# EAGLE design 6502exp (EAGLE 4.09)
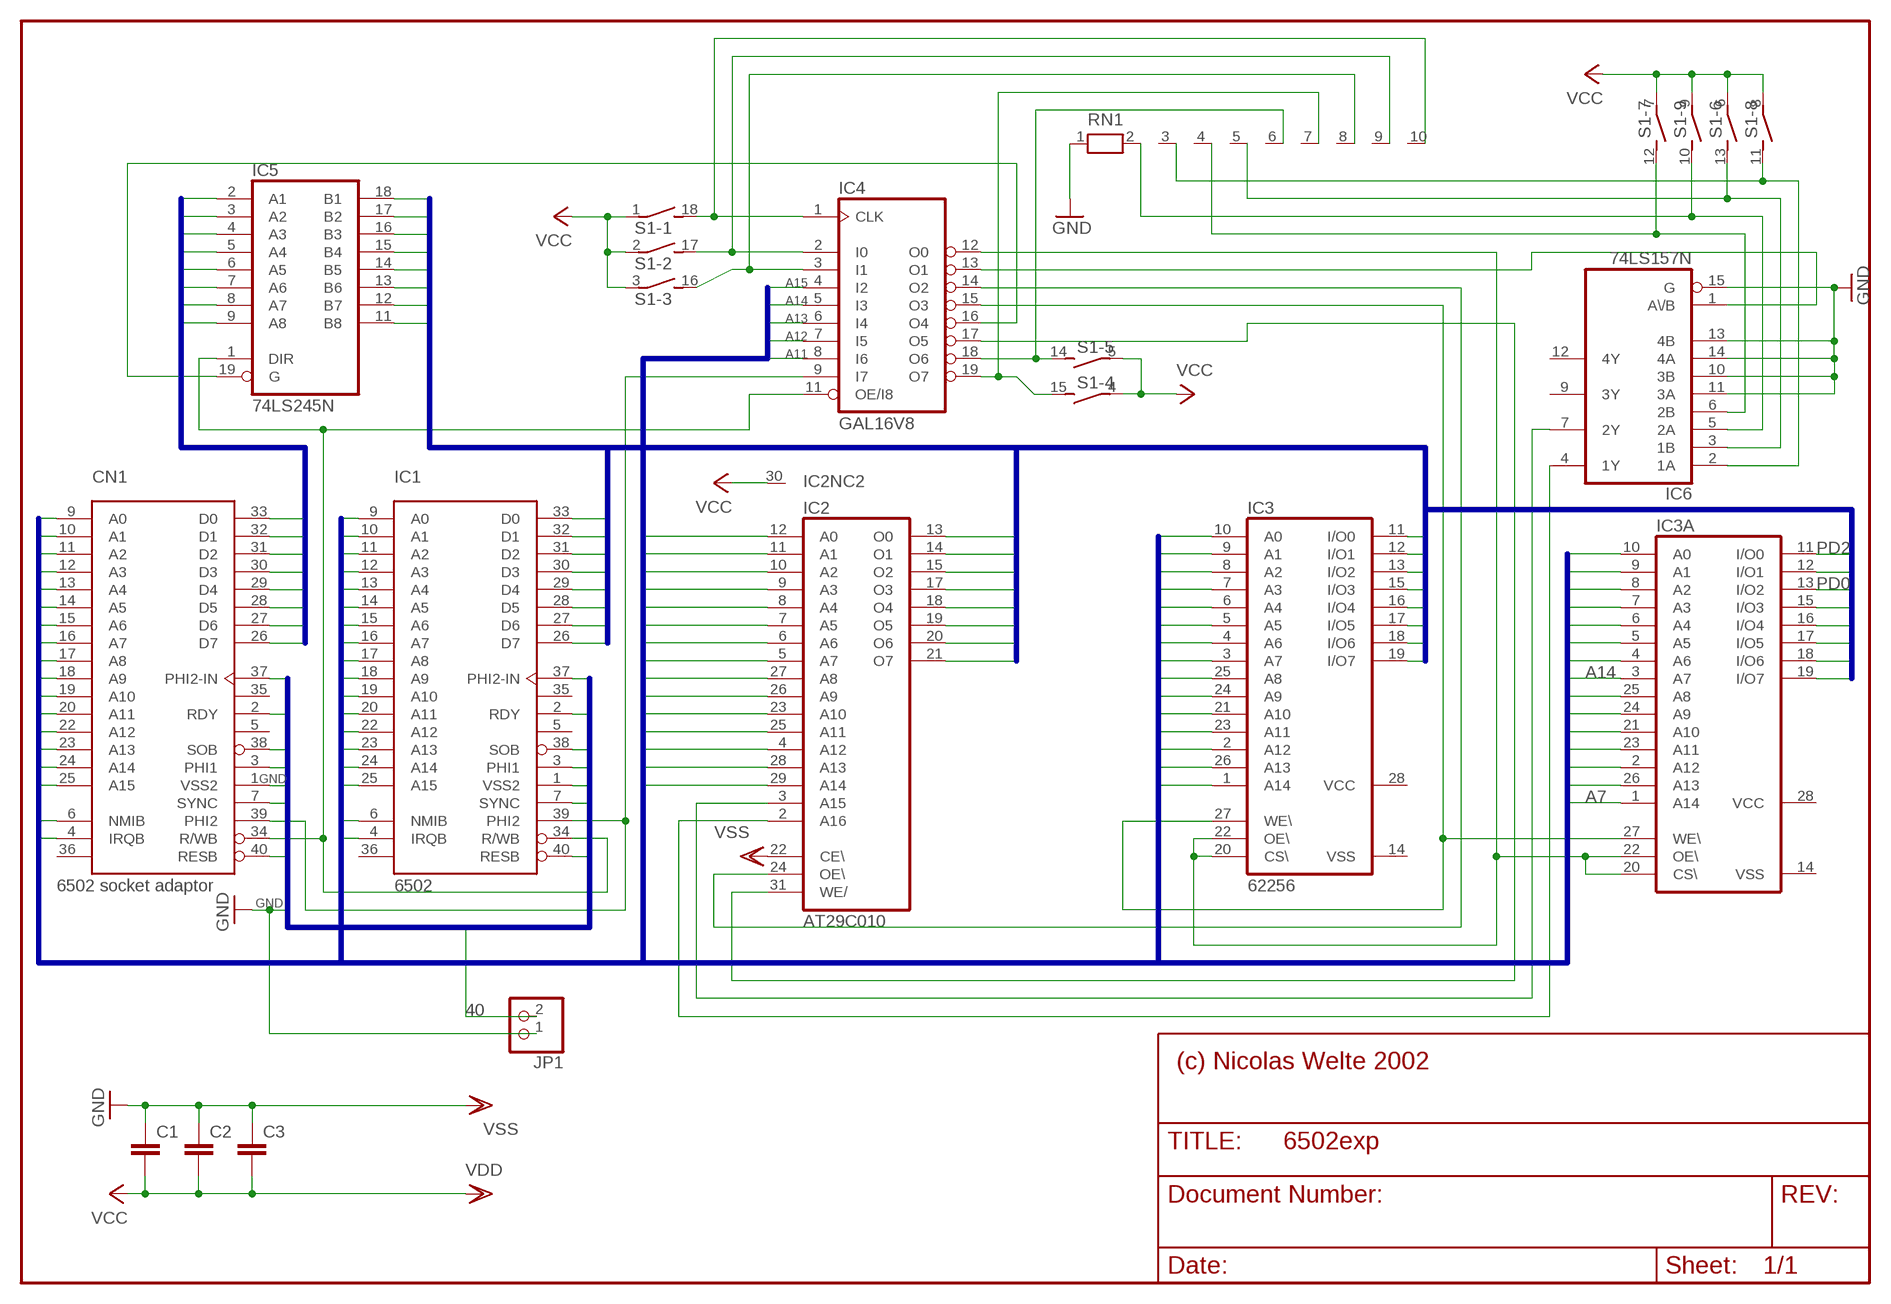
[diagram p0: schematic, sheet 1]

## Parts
C1  C5/3  [C5B3]
C2  C5/3  [C5B3]
C3  C5/3  [C5B3]
CN1  6502 socket adaptor  G65SC02P  [DIP-40]
IC1  6502  G65SC02P  [DIP-40]
IC2  AT29C010  AM29F010P  [DIL32-3]
IC3  62256  62256P  [DIL28-6]
IC3A  62256FP  [SO28L]
IC4  GAL16V8  16V8  [DIL20]
IC5  74LS245N  [DIL20]
IC6  74LS157N  [DIL16]
JP1  PINHD-1X2  [1X02]
RN1  RN09  [RN-10]
S1  DS09E  [DS-09]

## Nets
2: CN1.2(RDY) IC1.2(RDY)
3: CN1.3(PHI1) IC1.3(PHI1)
7: CN1.7(SYNC) IC1.7(SYNC)
37: CN1.37(PHI2-IN) IC1.37(PHI2-IN)
38: CN1.38(SOB) IC1.38(SOB)
40: CN1.40(RESB) IC1.40(RESB) JP1.2
A0: CN1.9(A0) IC1.9(A0) IC2.12(A0) IC3.10(A0) IC3A.10(A0)
A1: CN1.10(A1) IC1.10(A1) IC2.11(A1) IC3.9(A1) IC3A.9(A1)
A2: CN1.11(A2) IC1.11(A2) IC2.10(A2) IC3.8(A2) IC3A.8(A2)
A3: CN1.12(A3) IC1.12(A3) IC2.9(A3) IC3.7(A3) IC3A.7(A3)
A4: CN1.13(A4) IC1.13(A4) IC2.8(A4) IC3.6(A4) IC3A.6(A4)
A5: CN1.14(A5) IC1.14(A5) IC2.7(A5) IC3.5(A5) IC3A.5(A5)
A6: CN1.15(A6) IC1.15(A6) IC2.6(A6) IC3.4(A6) IC3A.4(A6)
A7: CN1.16(A7) IC1.16(A7) IC2.5(A7) IC3.3(A7) IC3A.1(A14)
A8: CN1.17(A8) IC1.17(A8) IC2.27(A8) IC3.25(A8) IC3A.25(A8)
A9: CN1.18(A9) IC1.18(A9) IC2.26(A9) IC3.24(A9) IC3A.24(A9)
A10: CN1.19(A10) IC1.19(A10) IC2.23(A10) IC3.21(A10) IC3A.21(A10)
A11: CN1.20(A11) IC1.20(A11) IC2.25(A11) IC3.23(A11) IC3A.23(A11) IC4.8(I6)
A12: CN1.22(A12) IC1.22(A12) IC2.4(A12) IC3.2(A12) IC3A.2(A12) IC4.7(I5)
A13: CN1.23(A13) IC1.23(A13) IC2.28(A13) IC3.26(A13) IC3A.26(A13) IC4.6(I4)
A14: CN1.24(A14) IC1.24(A14) IC2.29(A14) IC3.1(A14) IC3A.3(A7) IC4.5(I3)
A15: CN1.25(A15) IC1.25(A15) IC4.4(I2)
D0: CN1.33(D0) IC5.2(A1)
D1: CN1.32(D1) IC5.3(A2)
D2: CN1.31(D2) IC5.4(A3)
D3: CN1.30(D3) IC5.5(A4)
D4: CN1.29(D4) IC5.6(A5)
D5: CN1.28(D5) IC5.7(A6)
D6: CN1.27(D6) IC5.8(A7)
D7: CN1.26(D7) IC5.9(A8)
GND: C1.1 C2.1 C3.1 CN1.1(VSS2) IC1.1(VSS2) IC2.22(CE\) IC6.10(3B) IC6.11(3A) IC6.13(4B) IC6.14(4A) IC6.15(G) JP1.1 RN1.1 ; supply symbol labelled VSS
IRQ: CN1.4(IRQB) IC1.4(IRQB)
N$1: CN1.34(R/WB) IC1.34(R/WB) IC4.11(OE/I8) IC5.1(DIR)
N$2: IC4.3(I1) RN1.8 S1.16
N$3: CN1.39(PHI2) IC1.39(PHI2) IC4.9(I7)
N$4: IC4.2(I0) RN1.9 S1.17
N$5: IC4.1(CLK) RN1.10 S1.18
N$6: IC4.18(O6) RN1.6 S1.14
N$7: IC4.19(O7) RN1.7 S1.15
N$8: IC4.16(O4) IC5.19(G)
N$9: IC3.27(WE\) IC3A.27(WE\) IC4.15(O3)
N$10: IC2.24(OE\) IC4.14(O2)
N$11: IC2.31(WE/) IC4.17(O5)
N$12: IC4.13(O1) IC6.1(A\/B)
N$13: IC2.3(A15) IC6.7(2Y)
N$14: IC3.20(CS\) IC3.22(OE\) IC3A.20(CS\) IC3A.22(OE\) IC4.12(O0)
N$15: IC2.2(A16) IC6.4(1Y)
N$16: IC6.2(1A) RN1.3 S1.11
N$17: IC6.3(1B) RN1.5 S1.13
N$18: IC6.5(2A) RN1.2 S1.10
N$19: IC6.6(2B) RN1.4 S1.12
NMI: CN1.6(NMIB) IC1.6(NMIB)
PD0: IC1.33(D0) IC2.13(O0) IC3.11(I/O0) IC3A.13(I/O2) IC5.18(B1)
PD1: IC1.32(D1) IC2.14(O1) IC3.12(I/O1) IC3A.12(I/O1) IC5.17(B2)
PD2: IC1.31(D2) IC2.15(O2) IC3.13(I/O2) IC3A.11(I/O0) IC5.16(B3)
PD3: IC1.30(D3) IC2.17(O3) IC3.15(I/O3) IC3A.15(I/O3) IC5.15(B4)
PD4: IC1.29(D4) IC2.18(O4) IC3.16(I/O4) IC3A.16(I/O4) IC5.14(B5)
PD5: IC1.28(D5) IC2.19(O5) IC3.17(I/O5) IC3A.17(I/O5) IC5.13(B6)
PD6: IC1.27(D6) IC2.20(O6) IC3.18(I/O6) IC3A.18(I/O6) IC5.12(B7)
PD7: IC1.26(D7) IC2.21(O7) IC3.19(I/O7) IC3A.19(I/O7) IC5.11(B8)
VCC: C1.2 C2.2 C3.2 IC2.30(NC) S1.1 S1.2 S1.3 S1.4 S1.5 S1.6 S1.7 S1.8 S1.9 ; supply symbol labelled VDD
Unconnected: CN1.5(NC$3) CN1.35(NC$1) CN1.36(NC$2) IC1.5(NC$3) IC1.35(NC$1) IC1.36(NC$2) IC2.1(NC) IC6.9(3Y) IC6.12(4Y)

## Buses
D[0..7]
PD[0..7]
A[0..15],NMI,IRQ
37,2,38,3,1,7,40

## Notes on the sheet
- (c) Nicolas Welte 2002

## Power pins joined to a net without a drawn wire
GND: CN1.21(VSS) IC1.21(VSS) IC2.16(GND) IC3.14(VSS) IC3A.14(VSS) IC4.10(GND) IC5.10(GND) IC6.8(GND)
VCC: CN1.8(VDD) IC1.8(VDD) IC2.32(VCC) IC3.28(VCC) IC3A.28(VCC) IC4.20(VCC) IC5.20(VCC) IC6.16(VCC)

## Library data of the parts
C1-C3 = capacitor-wima:C: CAPACITOR
CN1 IC1 = 65XXX:G65SC02P
IC2 = am29-memory:AM29F010*: 1-Megabit FLASH MEMORY (128 K x 8 bit) 5 V-only
IC3 = memory-hitachi:62256P: MEMORY
IC3A = memory-hitachi:62256FP: MEMORY
IC4 = pal:16V8: PAL
IC5 = 74xx-eu:74*245: Octal BUS TRANSCEIVER, 3-state
IC6 = 74xx-eu:74*157: Quadruple 2-line to 1-line data SELECTOR/MULTIPLEXER
JP1 = pinhead:PINHD-1X2: PIN HEADER
RN1 = resistor-net:RN09: RESISTOR NETWORK
S1 = switch-dil:DS09E: DIL/CODE SWITCH

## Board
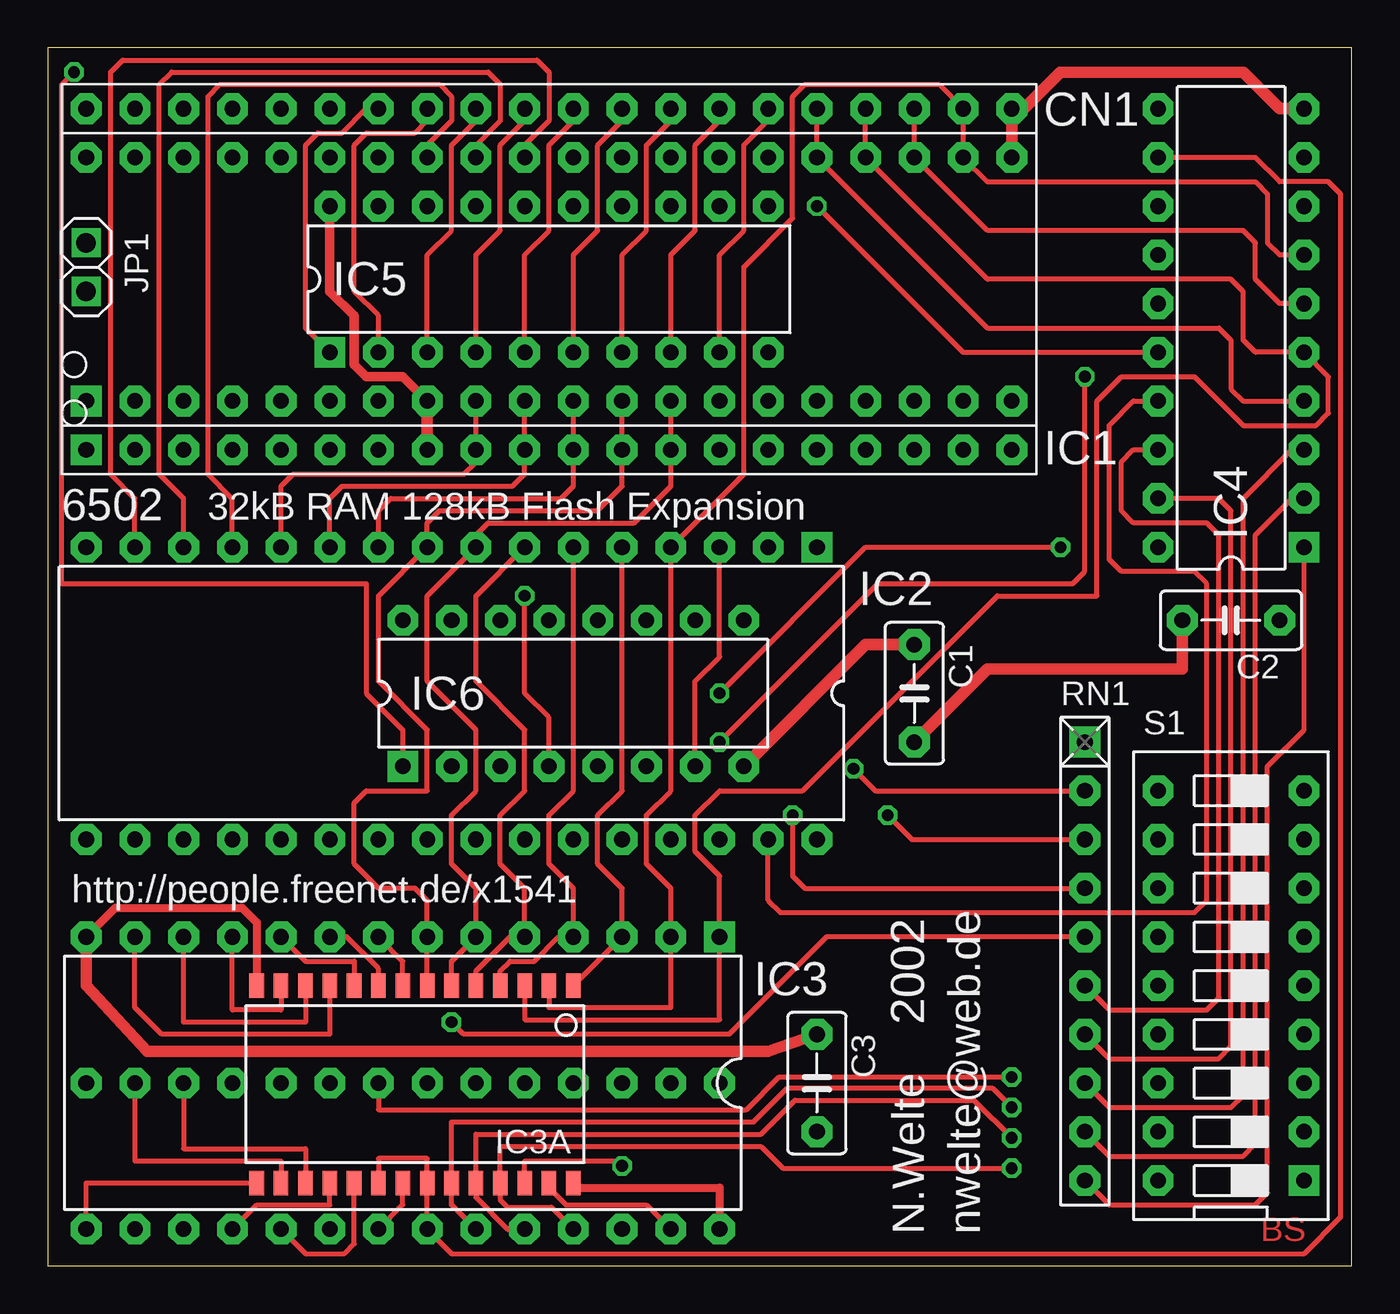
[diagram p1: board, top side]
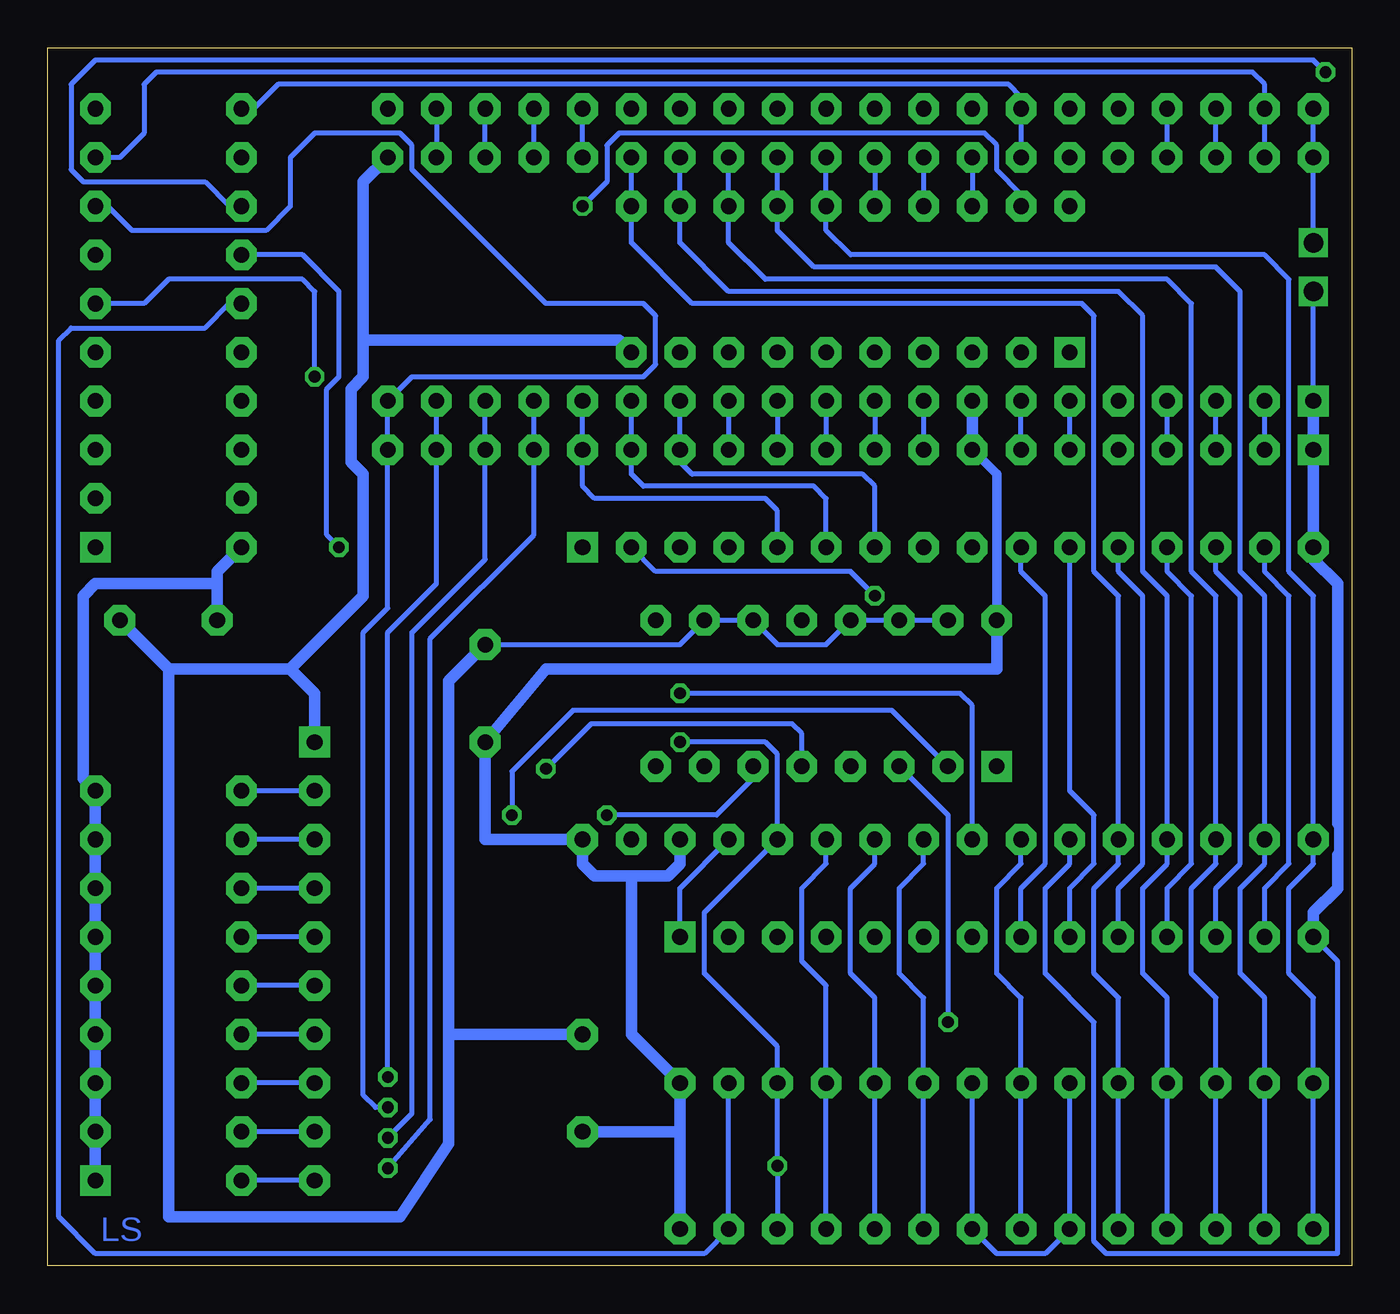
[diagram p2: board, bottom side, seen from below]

Size 67.97 x 63.49 mm. Coordinates in mm from the lower left corner, seen from the top.
Outline: 0,0 67.97,0 67.97,63.49 0,63.49 0,0
Copper layers used: Top, Bottom

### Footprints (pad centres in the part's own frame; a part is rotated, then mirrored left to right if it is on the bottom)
C5B3 = drill 0.813 pad 1.6 octagon: 1 -2.54,0; 2 2.54,0
DIP-40 = drill 0.813 pad 1.6 square: 1 -22.86,-7.62 | drill 0.813 pad 1.6 octagon: 2 -20.32,-7.62; 3 -17.78,-7.62; 4 -15.24,-7.62; 5 -12.7,-7.62; 6 -10.16,-7.62; 7 -7.62,-7.62; 8 -5.08,-7.62; 9 -2.54,-7.62; 10 0,-7.62; 11 2.54,-7.62; 12 5.08,-7.62; 13 7.62,-7.62; 14 10.16,-7.62; 15 12.7,-7.62; 16 15.24,-7.62; 17 17.78,-7.62; 18 20.32,-7.62; 19 22.86,-7.62; 20 25.4,-7.62; 21 25.4,7.62; 22 22.86,7.62; 23 20.32,7.62; 24 17.78,7.62; 25 15.24,7.62; 26 12.7,7.62; 27 10.16,7.62; 28 7.62,7.62; 29 5.08,7.62; 30 2.54,7.62; 31 0,7.62; 32 -2.54,7.62; 33 -5.08,7.62; 34 -7.62,7.62; 35 -10.16,7.62; 36 -12.7,7.62; 37 -15.24,7.62; 38 -17.78,7.62; 39 -20.32,7.62; 40 -22.86,7.62
DIL32-3 = drill 0.813 pad 1.6 square: 1 -19.05,-3.81 | drill 0.813 pad 1.6 octagon: 2 -16.51,-3.81; 3 -13.97,-3.81; 4 -11.43,-3.81; 5 -8.89,-3.81; 6 -6.35,-3.81; 7 -3.81,-3.81; 8 -1.27,-3.81; 9 1.27,-3.81; 10 3.81,-3.81; 11 6.35,-3.81; 12 8.89,-3.81; 13 11.43,-3.81; 14 13.97,-3.81; 15 16.51,-3.81; 16 19.05,-3.81; 17 19.05,11.43; 18 16.51,11.43; 19 13.97,11.43; 20 11.43,11.43; 21 8.89,11.43; 22 6.35,11.43; 23 3.81,11.43; 24 1.27,11.43; 25 -1.27,11.43; 26 -3.81,11.43; 27 -6.35,11.43; 28 -8.89,11.43; 29 -11.43,11.43; 30 -13.97,11.43; 31 -16.51,11.43; 32 -19.05,11.43
DIL28-6 = drill 0.813 pad 1.6 square: 1 -16.51,-7.62 | drill 0.813 pad 1.6 octagon: 2 -13.97,-7.62; 3 -11.43,-7.62; 4 -8.89,-7.62; 5 -6.35,-7.62; 6 -3.81,-7.62; 7 -1.27,-7.62; 8 1.27,-7.62; 9 3.81,-7.62; 10 6.35,-7.62; 11 8.89,-7.62; 12 11.43,-7.62; 13 13.97,-7.62; 14 16.51,-7.62; 15 16.51,7.62; 16 13.97,7.62; 17 11.43,7.62; 18 8.89,7.62; 19 6.35,7.62; 20 3.81,7.62; 21 1.27,7.62; 22 -1.27,7.62; 23 -3.81,7.62; 24 -6.35,7.62; 25 -8.89,7.62; 26 -11.43,7.62; 27 -13.97,7.62; 28 -16.51,7.62
SO28L = smd 0.762 x 1.27: 1 -7.62,-5.207; 2 -6.35,-5.207; 3 -5.08,-5.207; 4 -3.81,-5.207; 5 -2.54,-5.207; 6 -1.27,-5.207; 7 0,-5.207; 8 1.27,-5.207; 9 2.54,-5.207; 10 3.81,-5.207; 11 5.08,-5.207; 12 6.35,-5.207; 13 7.62,-5.207; 14 8.89,-5.207; 15 8.89,5.08; 16 7.62,5.08; 17 6.35,5.08; 18 5.08,5.08; 19 3.81,5.08; 20 2.54,5.08; 21 1.27,5.08; 22 0,5.08; 23 -1.27,5.08; 24 -2.54,5.08; 25 -3.81,5.08; 26 -5.08,5.08; 27 -6.35,5.08; 28 -7.62,5.08
DIL20 = drill 0.813 pad 1.6 square: 1 -11.43,-3.81 | drill 0.813 pad 1.6 octagon: 2 -8.89,-3.81; 3 -6.35,-3.81; 4 -3.81,-3.81; 5 -1.27,-3.81; 6 1.27,-3.81; 7 3.81,-3.81; 8 6.35,-3.81; 9 8.89,-3.81; 10 11.43,-3.81; 11 11.43,3.81; 12 8.89,3.81; 13 6.35,3.81; 14 3.81,3.81; 15 1.27,3.81; 16 -1.27,3.81; 17 -3.81,3.81; 18 -6.35,3.81; 19 -8.89,3.81; 20 -11.43,3.81
DIL16 = drill 0.813 pad 1.6 square: 1 -8.89,-3.81 | drill 0.813 pad 1.6 octagon: 2 -6.35,-3.81; 3 -3.81,-3.81; 4 -1.27,-3.81; 5 1.27,-3.81; 6 3.81,-3.81; 7 6.35,-3.81; 8 8.89,-3.81; 9 8.89,3.81; 10 6.35,3.81; 11 3.81,3.81; 12 1.27,3.81; 13 -1.27,3.81; 14 -3.81,3.81; 15 -6.35,3.81; 16 -8.89,3.81
1X02 = drill 1.016 square: 1 -1.27,0; 2 1.27,0
RN-10 = drill 0.813 pad 1.6 square: 1 -11.43,0 | drill 0.813 pad 1.6 octagon: 2 -8.89,0; 3 -6.35,0; 4 -3.81,0; 5 -1.27,0; 6 1.27,0; 7 3.81,0; 8 6.35,0; 9 8.89,0; 10 11.43,0
DS-09 = drill 0.813 pad 1.6 square: 1 -10.16,-3.81 | drill 0.813 pad 1.6 octagon: 2 -7.62,-3.81; 3 -5.08,-3.81; 4 -2.54,-3.81; 5 0,-3.81; 6 2.54,-3.81; 7 5.08,-3.81; 8 7.62,-3.81; 9 10.16,-3.81; 10 10.16,3.81; 11 7.62,3.81; 12 5.08,3.81; 13 2.54,3.81; 14 0,3.81; 15 -2.54,3.81; 16 -5.08,3.81; 17 -7.62,3.81; 18 -10.16,3.81

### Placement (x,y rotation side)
C1  45.17,29.84 270 top
C2  61.68,33.65 180 top
C3  40.09,9.52 270 top
CN1  24.85,52.7 0 top
IC1  24.85,50.16 0 top
IC2  21.04,33.65 180 top
IC3  18.5,9.52 180 top
IC3A  19.77,9.39 180 top
IC4  61.68,48.89 90 top
IC5  26.12,51.43 0 top
IC6  27.39,29.84 0 top
JP1  1.99,52.06 90 top
RN1  54.06,15.87 270 top
S1  61.68,14.6 90 top

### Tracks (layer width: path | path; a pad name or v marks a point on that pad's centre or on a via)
2
  Bottom 0.254: IC1.2 CN1.2
3
  Bottom 0.254: IC1.3 CN1.3
7
  Bottom 0.254: IC1.7 CN1.7
37
  Bottom 0.254: IC1.37 CN1.37
38
  Bottom 0.254: IC1.38 CN1.38
40
  Bottom 0.254: CN1.40 IC1.40 JP1.2
A0
  Top 0.254: IC2.12 12.15,40.63 12.79,41.27 21.68,41.27 22.31,41.9 CN1.9 | IC3A.10 15.96,15.87 13.42,15.87 IC3.10
  Bottom 0.254: IC2.12 12.15,36.19 10.88,34.92 10.88,20.95 12.15,19.68 IC3.10 | CN1.9 IC1.9
A1
  Top 0.254: IC2.11 14.69,40 15.33,40.63 24.22,40.63 24.85,41.27 CN1.10 | IC3A.9 17.23,15.49 15.58,17.14 IC3.9
  Bottom 0.254: IC3.9 14.69,19.68 13.42,20.95 13.42,23.49 14.69,24.76 IC2.11 | CN1.10 IC1.10
A2
  Top 0.254: IC2.10 17.23,39.36 17.87,40 26.76,40 27.39,40.63 CN1.11 | IC3A.8 18.5,15.87 IC3.8
  Bottom 0.254: IC3.8 17.23,19.68 15.96,20.95 15.96,34.92 17.23,36.19 IC2.10 | CN1.11 IC1.11
A3
  Top 0.254: CN1.12 29.93,40.63 28.66,39.36 20.41,39.36 19.77,38.73 IC2.9 17.23,34.92 17.23,30.48 19.77,27.94 19.77,24.76 16.6,24.76 15.96,24.12 15.96,20.95 17.23,19.68 19.14,19.68 19.77,19.05 IC3.7 IC3A.7
  Bottom 0.254: CN1.12 IC1.12
A4
  Top 0.254: CN1.13 32.47,40.63 30.57,38.73 22.95,38.73 22.31,38.09 IC2.8 19.77,34.92 19.77,30.48 22.31,27.94 22.31,24.76 21.04,23.49 21.04,20.95 22.31,19.68 IC3.6 21.04,15.87 IC3A.6
  Bottom 0.254: CN1.13 IC1.13
A5
  Top 0.254: IC2.7 22.31,34.92 22.31,30.48 24.85,27.94 24.85,24.76 23.58,23.49 23.58,20.95 24.85,19.68 IC3.5 24.09,17.14 22.31,15.36 IC3A.5
  Bottom 0.254: IC2.7 24.85,40.63 25.49,41.27 34.38,41.27 35.01,41.9 IC1.14 CN1.14
A6
  Top 0.254: IC2.6 27.39,24.76 26.12,23.49 26.12,20.95 27.39,19.68 IC3.4 26.63,17.14 25.36,15.87 24.09,15.87 23.58,15.36 IC3A.4
  Bottom 0.254: IC2.6 27.39,40 28.03,40.63 36.92,40.63 37.55,41.27 IC1.15 CN1.15
A7
  Top 0.254: IC2.5 29.93,24.76 28.66,23.49 28.66,20.95 29.93,19.68 IC3.3 IC3A.1
  Bottom 0.254: IC2.5 29.93,39.36 30.57,40 39.46,40 40.09,40.63 IC1.16 CN1.16
A8  (via drill 0.61, 0.81 pad 1.6)
  Top 0.254: v50.25,5.08 38.32,5.08 37.17,6.22 23.58,6.22 IC3A.25 23.58,3.42 23.96,3.04 26.25,3.04 IC3.25
  Bottom 0.254: IC3.25 v27.39,9.52 27.39,14.6 28.66,15.87 28.66,19.68 27.39,20.95 IC2.27 | CN1.17 IC1.17 42.63,38.09 48.03,32.7 48.03,7.62 v50.25,5.08
A9  (via drill 0.61, 0.81 pad 1.6)
  Top 0.254: v50.25,6.66 48.29,8.63 38.95,8.63 37.17,6.85 22.31,6.85 IC3A.24 22.31,3.55 23.96,1.9 IC3.24 24.98,1.9
  Bottom 0.254: IC3.24 v24.85,9.52 24.85,13.96 26.12,15.23 26.12,19.68 24.85,20.95 IC2.26 | CN1.18 IC1.18 45.17,36.82 48.98,33.02 48.98,7.93 v50.25,6.66
A10  (via drill 0.61, 0.81 pad 1.6)
  Top 0.254: v50.25,9.84 38.12,9.84 36.41,8.12 17.23,8.12 v17.23,9.52 | IC3.21 18.5,3.17 IC3A.21
  Bottom 0.254: IC2.23 17.23,20.95 18.5,19.68 18.5,15.23 17.23,13.96 v17.23,9.52 IC3.21 | CN1.19 IC1.19 47.71,35.55 50.25,33.02 v50.25,9.84
A11  (via drill 0.61, 0.81 pad 1.6)
  Top 0.254: v50.25,8.25 49.24,9.27 38.57,9.27 36.79,7.49 21.04,7.49 21.04,4.19 | IC3.23 21.04,3.17 21.04,4.19 | 21.04,4.19 IC3A.23
  Bottom 0.254: IC2.25 22.31,20.95 23.58,19.68 23.58,15.23 22.31,13.96 v22.31,9.52 IC3.23 | IC4.8 64.86,55.24 63.59,53.97 56.6,53.97 55.33,55.24 55.33,57.78 54.06,59.05 49.62,59.05 48.98,58.41 48.98,57.14 42,50.16 36.92,50.16 36.28,49.52 36.28,46.98 36.92,46.35 48.98,46.35 CN1.20 IC1.20 50.25,34.28 51.52,33.02 51.52,8.88 50.89,8.25 v50.25,8.25
A12
  Top 0.254: IC4.7 64.22,52.7 63.59,53.34 63.59,55.88 62.95,56.51 48.98,56.51 IC1.22 CN1.22 46.44,61.59 39.46,61.59 38.82,60.95 38.82,54.6 36.28,52.06 36.28,41.27 IC2.4 32.47,24.76 31.2,23.49 31.2,20.95 32.47,19.68 IC3.2 32.47,13.46 26.12,13.46 IC3A.2
  Bottom 0.254: CN1.22 IC1.22
A13  (via drill 0.61, 0.81 pad 1.6)
  Top 0.254: v35.01,27.3 43.27,35.55 53.43,35.55 54.06,36.19 v54.06,46.35 | IC4.6 64.22,50.16 62.95,51.43 62.95,53.34 62.32,53.97 48.98,53.97 IC1.23 CN1.23 | v29.93,5.2 29.93,5.46 24.85,5.46 IC3A.26
  Bottom 0.254: IC1.23 CN1.23 | v35.01,27.3 30.57,27.3 29.93,26.67 IC2.28 33.74,18.41 33.74,15.23 29.93,11.42 v29.93,9.52 v29.93,5.2 IC3.26 | v54.06,46.35 54.06,50.79 54.7,51.43 61.68,51.43 62.95,50.16 IC4.6
A14
  Top 0.254: CN1.24 IC1.24 48.98,51.43 61.68,51.43 62.32,50.79 62.32,48.25 62.95,47.62 IC4.5 66.76,46.35 66.76,44.45 66.13,43.81 62.32,43.81 59.78,46.35 55.97,46.35 54.7,45.08 54.7,34.92 49.49,34.92 39.33,24.76 35.01,24.76 33.74,23.49 33.74,21.59 35.01,20.32 IC3.1 35.01,12.82 24.85,12.82 IC3A.3
  Bottom 0.254: IC1.24 CN1.24 | IC3.1 35.01,19.68 IC2.29
A15
  Top 0.254: IC4.4 62.32,45.08 61.68,45.71 61.68,48.25 61.05,48.89 48.98,48.89 IC1.25 CN1.25
  Bottom 0.254: IC1.25 CN1.25
D0
  Top 0.254: CN1.33 19.77,59.68 19.14,59.05 16.6,59.05 15.96,58.41 15.96,50.79 17.23,49.52 IC5.2
D1
  Top 0.254: IC5.3 19.77,52.7 21.04,53.97 21.04,58.41 22.31,59.68 CN1.32
D2
  Top 0.254: IC5.4 22.31,52.7 23.58,53.97 23.58,58.41 24.85,59.68 CN1.31
D3
  Top 0.254: IC5.5 24.85,52.7 26.12,53.97 26.12,58.41 27.39,59.68 CN1.30
D4
  Top 0.254: IC5.6 27.39,52.7 28.66,53.97 28.66,58.41 29.93,59.68 CN1.29
D5
  Top 0.254: IC5.7 29.93,52.7 31.2,53.97 31.2,58.41 32.47,59.68 CN1.28
D6
  Top 0.254: IC5.8 32.47,52.7 33.74,53.97 33.74,58.41 35.01,59.68 CN1.27
D7
  Top 0.254: IC5.9 35.01,52.7 36.28,53.97 36.28,58.41 37.55,59.68 CN1.26
GND
  Top 0.406: IC3A.14 10.88,17.9 10.12,18.66 3.52,18.66 IC3.14
  Top 0.61: IC4.10 64.22,60.32 62.32,62.22 52.79,62.22 50.89,60.32 CN1.21 IC1.21 | IC6.8 42.63,32.38 C1.1 | IC3.14 1.99,14.6 5.17,11.17 37.55,11.17 C3.1
  Bottom 0.254: IC6.15 IC6.14 IC6.13 27.39,32.38 29.93,32.38 IC6.11 IC6.10 35.01,32.38 C1.1 | IC2.22 14.69,20.95 15.96,19.68 15.96,15.23 13.42,12.69 13.42,1.27 12.79,0.63 0.72,0.63 0.72,15.87 IC3.14 | CN1.1 JP1.1
  Bottom 0.406: 0.72,21.41 0.67,21.41 | 0.67,23.49 0.72,23.06 | 1.99,36.82 IC2.16
  Bottom 0.508: 0.67,21.41 0.67,23.49
  Bottom 0.61: 51.52,48.25 38.19,48.25 IC5.10 | 51.52,48.25 51.52,56.51 IC1.21 | 0.72,21.41 0.72,19.68 1.99,18.41 IC3.14 | 0.72,23.06 0.72,35.55 1.99,36.82 | CN1.1 IC1.1 IC2.16 | C1.1 47.08,30.48 47.08,12.06 | 47.08,12.06 47.08,6.34 49.62,2.54 61.68,2.54 61.68,31.11 | C3.1 47.08,12.06 | 51.52,48.25 51.52,46.35 52.16,45.71 52.16,41.9 51.52,41.27 51.52,34.92 55.33,31.11 | 61.68,31.11 55.33,31.11 | 61.68,31.11 C2.1 | RN1.1 54.06,29.84 55.33,31.11
IRQ
  Bottom 0.254: IC1.4 CN1.4
N$1
  Top 0.254: IC5.1 13.42,48.89 13.42,58.41 14.06,59.05 15.33,59.05 16.6,60.32 CN1.34
  Bottom 0.254: IC4.11 57.24,60.32 55.97,61.59 17.87,61.59 17.23,60.95 CN1.34 IC1.34
N$2
  Top 0.254: IC4.3 64.86,42.54 62.32,40 62.32,8.88 61.68,8.25 55.33,8.25 RN1.8
  Bottom 0.254: RN1.8 S1.16
N$3
  Bottom 0.254: IC1.39 CN1.39 4.53,61.59 5.17,62.22 62.32,62.22 62.95,61.59 62.95,59.05 64.22,57.78 IC4.9
N$4
  Top 0.254: IC4.2 64.86,40 62.95,38.09 62.95,6.34 62.32,5.71 55.33,5.71 RN1.9
  Bottom 0.254: RN1.9 S1.17
N$5
  Top 0.254: IC4.1 65.49,27.94 63.59,26.03 63.59,3.81 62.95,3.17 55.33,3.17 RN1.10
  Bottom 0.254: RN1.10 S1.18
N$6
  Top 0.254: IC4.18 56.6,42.54 55.97,41.9 55.97,39.36 56.6,38.73 60.41,38.73 61.05,38.09 61.05,13.96 60.41,13.33 55.33,13.33 RN1.6
  Bottom 0.254: RN1.6 S1.14
N$7
  Top 0.254: IC4.19 61.05,40 61.68,39.36 61.68,11.42 61.05,10.79 55.33,10.79 RN1.7
  Bottom 0.254: RN1.7 S1.15
N$8  (via drill 0.61)
  Top 0.254: v40.09,55.24 47.71,47.62 IC4.16
  Bottom 0.254: v40.09,55.24 38.82,56.51 38.82,58.41 38.19,59.05 19.14,59.05 18.5,58.41 18.5,57.14 17.23,55.88 IC5.19
N$9  (via drill 0.81 pad 1.6)
  Top 0.254: IC3A.27 26.12,4.06 27.01,3.17 31.2,3.17 IC3.27
  Bottom 0.254: IC4.15 58.51,50.16 59.78,48.89 66.76,48.89 67.4,48.25 67.4,2.54 65.49,0.63 33.74,0.63 IC3.27 v32.47,9.52
N$10  (via drill 0.61)
  Top 0.254: v52.79,37.46 42.63,37.46 v35.01,29.84
  Bottom 0.254: IC4.14 54.7,52.7 52.79,50.79 52.79,46.35 53.43,45.71 53.43,38.09 v52.79,37.46 | v35.01,29.84 20.41,29.84 19.77,29.21 IC2.24
N$11
  Top 0.254: IC4.17 56.6,45.08 55.33,43.81 55.33,36.82 55.97,36.19 59.78,36.19 60.41,35.55 60.41,19.05 59.78,18.41 38.19,18.41 37.55,19.05 IC2.31
N$12  (via drill 0.61)
  Top 0.254: IC6.1 18.5,27.94 16.6,29.84 16.6,35.55 0.72,35.55 0.72,61.59 v1.36,62.22
  Bottom 0.254: v1.36,62.22 1.99,62.86 65.49,62.86 66.76,61.59 66.76,57.14 66.13,56.51 59.78,56.51 58.51,55.24 IC4.13
N$13
  Top 0.254: IC6.7 33.74,30.48 35.01,31.75 IC2.3
N$14  (via drill 0.81 pad 1.6)
  Top 0.254: IC4.12 62.95,57.78 64.22,56.51 66.76,56.51 67.4,55.88 67.4,2.54 65.49,0.63 21.04,0.63 IC3.22 IC3A.22 19.77,5.58 17.23,5.58 IC3A.20 17.11,4.31
  Bottom 0.254: v19.77,9.52 IC3.22 18.5,0.63 15.96,0.63 IC3.20 | IC3.20 v14.69,9.52 IC3.20
N$15  (via drill 0.61)
  Top 0.254: IC6.4 26.12,28.57 24.85,29.84 v24.85,34.92
  Bottom 0.254: v24.85,34.92 26.12,36.19 36.28,36.19 IC2.2
N$16  (via drill 0.61)
  Top 0.254: RN1.3 45.05,22.22 v43.78,23.49
  Bottom 0.254: RN1.3 S1.11 | IC6.2 23.96,28.95 40.6,28.95 43.78,25.78 v43.78,23.49
N$17  (via drill 0.61)
  Top 0.254: RN1.5 40.6,17.14 35.52,12.06 21.68,12.06 v21.04,12.69
  Bottom 0.254: RN1.5 S1.13 | IC6.3 21.04,23.49 v21.04,12.69
N$18  (via drill 0.61)
  Top 0.254: v42,25.9 43.14,24.76 RN1.2
  Bottom 0.254: RN1.2 S1.10 | IC6.5 28.66,27.75 29.17,28.25 39.65,28.25 v42,25.9
N$19  (via drill 0.61)
  Top 0.254: RN1.4 39.46,19.68 38.82,20.32 v38.82,23.49
  Bottom 0.254: v38.82,23.49 33.11,23.49 31.2,25.39 IC6.6 | RN1.4 S1.12
NMI
  Bottom 0.254: IC1.6 CN1.6
PD0
  Top 0.254: IC2.13 9.61,40 8.34,41.27 8.34,60.95 8.98,61.59 20.41,61.59 21.04,60.95 21.04,59.68 19.77,58.41 IC1.33 | IC3A.13 12.15,13.33 9.61,13.33 IC3.11
  Bottom 0.254: IC2.13 9.61,36.19 8.34,34.92 8.34,20.95 9.61,19.68 IC3.11 | IC1.33 IC5.18
PD1
  Top 0.254: IC2.14 7.07,40 5.8,41.27 5.8,61.59 6.44,62.22 22.95,62.22 23.58,61.59 23.58,59.68 22.31,58.41 IC1.32 | IC3A.12 13.42,12.69 7.07,12.69 IC3.12
  Bottom 0.254: IC2.14 7.07,36.19 5.8,34.92 5.8,20.95 7.07,19.68 IC3.12 | IC1.32 IC5.17
PD2
  Top 0.254: IC2.15 4.53,40 3.26,41.27 3.26,62.22 3.9,62.86 25.49,62.86 26.12,62.22 26.12,59.68 24.85,58.41 IC1.31 | IC3A.11 14.69,12.06 5.93,12.06 4.53,13.46 IC3.13
  Bottom 0.254: IC2.15 4.53,36.19 3.26,34.92 3.26,20.95 4.53,19.68 IC3.13 | IC1.31 IC5.16
PD3  (via drill 0.81 pad 1.6)
  Top 0.254: IC3A.15 1.99,4.31 IC3.15
  Bottom 0.254: IC3.15 v1.99,9.52 1.99,13.96 3.26,15.23 3.26,19.68 1.99,20.95 IC2.17 1.99,34.92 3.26,36.19 3.26,51.43 4.53,52.7 26.12,52.7 27.39,53.97 IC5.15 IC1.30
PD4  (via drill 0.81 pad 1.6)
  Top 0.254: IC3A.16 12.15,5.46 4.53,5.46 v4.53,9.52
  Bottom 0.254: IC3.16 v4.53,9.52 4.53,13.96 5.8,15.23 5.8,19.68 4.53,20.95 IC2.18 4.53,34.92 5.8,36.19 5.8,50.79 7.07,52.06 28.03,52.06 29.93,53.97 IC5.14 IC1.29
PD5  (via drill 0.81 pad 1.6)
  Top 0.254: IC3A.17 13.42,6.09 7.07,6.09 v7.07,9.52
  Bottom 0.254: IC3.17 v7.07,9.52 7.07,13.96 8.34,15.23 8.34,19.68 7.07,20.95 IC2.19 7.07,34.92 8.34,36.19 8.34,50.16 9.61,51.43 30.57,51.43 32.47,53.34 IC5.13 IC1.28
PD6  (via drill 0.81 pad 1.6)
  Top 0.254: IC3A.18 14.69,3.17 10.88,3.17 IC3.18
  Bottom 0.254: IC3.18 v9.61,9.52 9.61,13.96 10.88,15.23 10.88,19.68 9.61,20.95 IC2.20 9.61,34.92 10.88,36.19 10.88,49.52 12.15,50.79 32.47,50.79 35.01,53.34 IC5.12 IC1.27
PD7  (via drill 0.81 pad 1.6)
  Top 0.254: IC3A.19 15.96,1.14 15.46,0.63 13.42,0.63 IC3.19
  Bottom 0.254: IC3.19 v12.15,9.52 12.15,13.96 13.42,15.23 13.42,19.68 12.15,20.95 IC2.21 12.15,34.92 13.42,36.19 13.42,49.52 14.06,50.16 34.38,50.16 37.55,53.34 IC5.11 IC1.26
VCC  (via drill 0.81 pad 1.6)
  Top 0.254: IC3A.28 27.77,4.06
  Top 0.406: 27.77,4.06 35.01,4.06 IC3.28
  Top 0.508: IC5.20 14.69,50.79 15.96,49.52 15.96,46.98 16.6,46.35 18.5,46.35 CN1.8
  Top 0.61: C2.2 59.14,31.11 48.98,31.11 C1.2 | IC1.8 CN1.8
  Bottom 0.254: 45.17,26.67 C1.2
  Bottom 0.508: IC6.16 18.5,41.27 IC1.8
  Bottom 0.61: IC4.20 59.14,36.19 59.14,35.55 | C2.2 59.14,35.55 | 45.17,26.67 45.17,22.22 IC2.32 40.09,20.95 39.46,20.32 37.55,20.32 | IC6.16 18.5,31.11 42,31.11 C1.2 | IC1.8 CN1.8 | IC2.30 35.01,20.95 35.65,20.32 37.55,20.32 | IC3.28 35.01,6.98 | 35.01,6.98 v35.01,9.52 37.55,12.06 37.55,20.32 | 35.01,6.98 C3.2 | S1.1 S1.2 S1.3 S1.4 S1.5 S1.6 S1.7 S1.8 S1.9 66.13,25.39 66.13,34.92 65.49,35.55 59.14,35.55

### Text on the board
Top: BS
Bottom: LS
tNames: 6502 | 32kB RAM 128kB Flash Expansion | http://people.freenet.de/x1541 | 2002 | N.Welte | nwelte@web.de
